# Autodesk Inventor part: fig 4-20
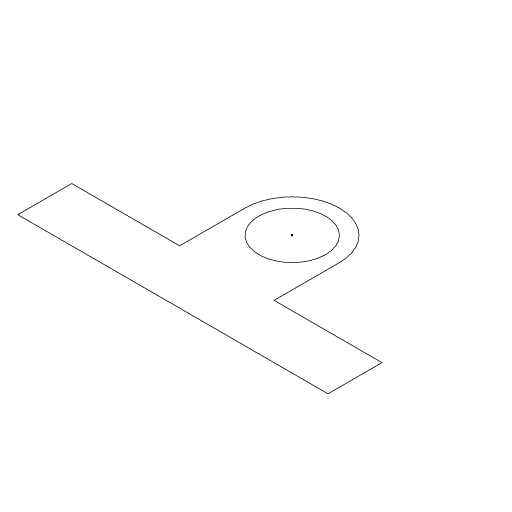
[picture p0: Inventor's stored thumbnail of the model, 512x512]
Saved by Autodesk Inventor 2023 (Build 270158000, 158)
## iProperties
Created: 2004-05
Part Number: fig 4-20
Document SubType Name: Modeling
Designer: CADCIM Technologies
Manufacturer: Standard
Standards Organization: Custom
Density: 1 g/cm^3
Material: Generic
Appearance: Default
Author: CADCIM Technologies
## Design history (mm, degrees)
sketch "Sketch1"
  geometry: L1 (21.396, 25)-(21.396, 15.181); L2 (21.396, 15.181)-(77.829, 15.181); L3 (77.829, 15.181)-(77.829, 25); L4 (77.829, 25)-(58.204, 25); L5 (58.204, 25)-(58.204, 36.886); L6 (41.021, 36.886)-(41.021, 25); L7 (41.021, 25)-(21.396, 25); C1 r 6.072 at (49.612, 36.886); A1 r 8.592 centre (49.612, 36.886) between (58.204, 36.886) and (41.021, 36.886)
  constraints: 14 end point, 5 parallel, 2 centre point, 2 equal length, 2 point on circle, 2 tangent, 1 coincident, 1 perpendicular, 1 vertical, 1 other
